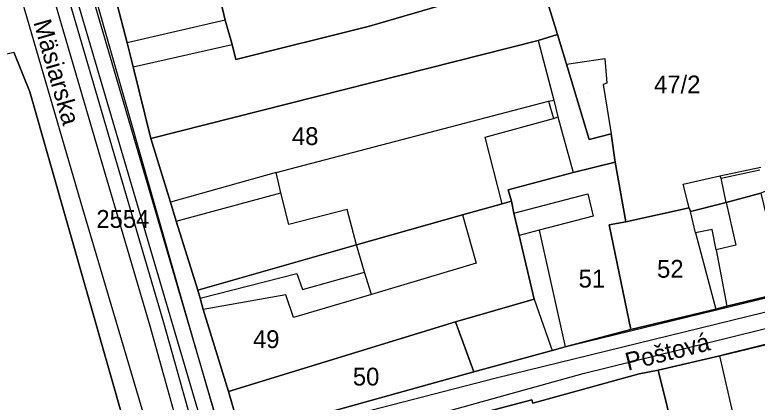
# Model space of a CAD drawing. Extents: x -263423 to -261326, y -1240067 to -1237864.
# Drawn here: x -263040 to -262956.7, y -1239293 to -1239249.5 of the extents above; entities that cross this region are included whole.
import ezdxf

# ---------------------------------------------------------------- set-up
doc = ezdxf.new("R2010")
doc.units = 0
for name, color, linetype in [('body_kn', 7, 'Continuous'), ('kladpar_druhypozemkov', 7, 'Continuous'), ('kladpar_hranice', 7, 'Continuous'), ('kladpar_parcelnecisla', 7, 'Continuous'), ('kladpar_plochy', 7, 'Continuous'), ('popisy', 7, 'Continuous'), ('tarchy_linie', 7, 'Continuous'), ('zappar_hrandruhpozemk', 7, 'Continuous')]:
    doc.layers.add(name, color=color, linetype=linetype)

msp = doc.modelspace()

# ---------------------------------------------------------------- linework, layer by layer
at = {"layer": 'body_kn'}
for p, q in [((-263016.37, -1239250.11), (-263016.37, -1239250.11)), ((-263016.37, -1239250.11), (-263016.37, -1239250.11)), ((-263000.2, -1239250.78), (-263000.2, -1239250.78)), ((-262981.26, -1239252.4), (-262981.26, -1239252.4)), ((-262981.26, -1239252.4), (-262981.26, -1239252.4)), ((-262979.09, -1239251.74), (-262979.09, -1239251.74)), ((-263027.4, -1239252.66), (-263027.4, -1239252.66)), ((-263015.6, -1239252.86), (-263015.6, -1239252.86)), ((-263015.2, -1239254.52), (-263015.2, -1239254.52)), ((-262973.76, -1239254.4), (-262973.76, -1239254.4)), ((-263026.7, -1239255.35), (-263026.7, -1239255.35)), ((-263026.7, -1239255.35), (-263026.7, -1239255.35)), ((-262978.09, -1239255.07), (-262978.09, -1239255.07)), ((-262978.09, -1239255.07), (-262978.09, -1239255.07)), ((-262973.95, -1239257.32), (-262973.95, -1239257.32)), ((-262973.56, -1239257.2), (-262973.56, -1239257.2)), ((-263038.31, -1239258.15), (-263038.31, -1239258.15)), ((-262979.51, -1239259.11), (-262979.51, -1239259.11)), ((-262979.51, -1239259.11), (-262979.51, -1239259.11)), ((-262980.08, -1239259.22), (-262980.08, -1239259.22)), ((-262979.55, -1239261.14), (-262979.55, -1239261.14)), ((-262979.55, -1239261.14), (-262979.55, -1239261.14)), ((-262979.04, -1239260.96), (-262979.04, -1239260.96)), ((-262987.21, -1239263.26), (-262987.21, -1239263.26)), ((-262973.05, -1239262.87), (-262973.05, -1239262.87)), ((-263024.72, -1239263.4), (-263024.72, -1239263.4)), ((-262975.54, -1239263.51), (-262975.54, -1239263.51)), ((-263030.37, -1239265.53), (-263030.37, -1239265.53)), ((-263028.88, -1239265.09), (-263028.88, -1239265.09)), ((-262972.62, -1239266.06), (-262972.62, -1239266.06)), ((-263010.65, -1239267.2), (-263010.65, -1239267.2)), ((-262977.34, -1239267.22), (-262977.34, -1239267.22)), ((-262977.34, -1239267.22), (-262977.34, -1239267.22)), ((-262960.85, -1239267.58), (-262960.85, -1239267.58)), ((-262960.73, -1239267.84), (-262960.73, -1239267.84)), ((-262960.73, -1239267.84), (-262960.73, -1239267.84)), ((-262984.61, -1239269.16), (-262984.61, -1239269.16)), ((-262964.99, -1239268.51), (-262964.99, -1239268.51)), ((-263010.13, -1239269.5), (-263010.13, -1239269.5)), ((-262975.68, -1239269.61), (-262975.68, -1239269.61)), ((-263022.53, -1239270.56), (-263022.53, -1239270.56)), ((-262985.28, -1239270.74), (-262985.28, -1239270.74)), ((-262985.28, -1239270.74), (-262985.28, -1239270.74)), ((-262984.26, -1239270.44), (-262984.26, -1239270.44)), ((-262960.15, -1239270.58), (-262960.15, -1239270.58)), ((-262960.15, -1239270.58), (-262960.15, -1239270.58)), ((-263032.38, -1239271.3), (-263032.38, -1239271.3)), ((-263002.68, -1239271.38), (-263002.68, -1239271.38)), ((-262964.29, -1239271.19), (-262964.29, -1239271.19)), ((-262964.29, -1239271.19), (-262964.29, -1239271.19)), ((-262964.17, -1239271.58), (-262964.17, -1239271.58)), ((-262989.75, -1239271.97), (-262989.75, -1239271.97)), ((-262989.75, -1239271.97), (-262989.75, -1239271.97)), ((-262983.97, -1239271.78), (-262983.97, -1239271.78)), ((-262983.97, -1239271.78), (-262983.97, -1239271.78)), ((-262975.1, -1239272.1), (-262975.1, -1239272.1)), ((-263021.88, -1239272.67), (-263021.88, -1239272.67)), ((-263021.88, -1239272.67), (-263021.88, -1239272.67)), ((-263009.26, -1239273.07), (-263009.26, -1239273.07)), ((-262973.28, -1239273.1), (-262973.28, -1239273.1)), ((-262971.43, -1239272.75), (-262971.43, -1239272.75)), ((-262981.16, -1239273.69), (-262981.16, -1239273.69)), ((-262963.59, -1239274), (-262963.59, -1239274)), ((-262961.74, -1239273.6), (-262961.74, -1239273.6)), ((-262983.39, -1239274.27), (-262983.39, -1239274.27)), ((-263001.63, -1239275.34), (-263001.63, -1239275.34)), ((-263001.63, -1239275.34), (-263001.63, -1239275.34)), ((-262959.05, -1239275.37), (-262959.05, -1239275.37)), ((-262961.28, -1239275.9), (-262961.28, -1239275.9)), ((-262961.28, -1239275.9), (-262961.28, -1239275.9)), ((-262988.22, -1239277.41), (-262988.22, -1239277.41)), ((-263008.36, -1239278.56), (-263008.36, -1239278.56)), ((-263000.74, -1239278.41), (-263000.74, -1239278.41)), ((-263019.44, -1239280.42), (-263019.44, -1239280.42)), ((-263007.7, -1239280.35), (-263007.7, -1239280.35)), ((-263019.21, -1239281.31), (-263019.21, -1239281.31)), ((-263019.21, -1239281.31), (-263019.21, -1239281.31)), ((-263009.56, -1239280.95), (-263009.56, -1239280.95)), ((-262999.97, -1239280.9), (-262999.97, -1239280.9)), ((-262981.71, -1239281.43), (-262981.71, -1239281.43)), ((-262981.71, -1239281.43), (-262981.71, -1239281.43)), ((-263021.19, -1239281.84), (-263021.19, -1239281.84)), ((-262960.09, -1239282.21), (-262960.09, -1239282.21)), ((-263018.86, -1239282.59), (-263018.86, -1239282.59)), ((-262961.3, -1239282.57), (-262961.3, -1239282.57)), ((-262961.3, -1239282.57), (-262961.3, -1239282.57)), ((-263023.3, -1239284.05), (-263023.3, -1239284.05)), ((-263008.72, -1239283.51), (-263008.72, -1239283.51)), ((-262990.52, -1239283.97), (-262990.52, -1239283.97)), ((-262990.52, -1239283.97), (-262990.52, -1239283.97)), ((-263024.79, -1239284.47), (-263024.79, -1239284.47)), ((-262970.87, -1239284.84), (-262970.87, -1239284.84)), ((-262977.34, -1239286.55), (-262977.34, -1239286.55)), ((-262979.68, -1239287.19), (-262979.68, -1239287.19)), ((-262978.21, -1239286.78), (-262978.21, -1239286.78)), ((-262960.85, -1239287.79), (-262960.85, -1239287.79)), ((-262960.14, -1239287.62), (-262960.14, -1239287.62)), ((-262988.49, -1239289.6), (-262988.49, -1239289.6)), ((-262976.2, -1239289.79), (-262976.2, -1239289.79)), ((-262969.9, -1239289.82), (-262969.9, -1239289.82)), ((-262967.8, -1239289.42), (-262967.8, -1239289.42)), ((-262985.96, -1239290.25), (-262985.96, -1239290.25)), ((-263016.01, -1239291.8), (-263016.01, -1239291.8)), ((-262981.96, -1239292.73), (-262981.96, -1239292.73)), ((-262981.96, -1239292.73), (-262981.96, -1239292.73))]:
    msp.add_line(p, q, dxfattribs=at)
at = {"layer": 'kladpar_druhypozemkov'}
for p, q in [((-262965.58, -1239256.03), (-262965.58, -1239256.03)), ((-262975.74, -1239258.24), (-262975.74, -1239258.24)), ((-263007.48, -1239262.23), (-263007.48, -1239262.23)), ((-263027.11, -1239271.58), (-263027.11, -1239271.58)), ((-262966.58, -1239277.03), (-262966.58, -1239277.03)), ((-262975.98, -1239278.03), (-262975.98, -1239278.03)), ((-263012.08, -1239285.23), (-263012.08, -1239285.23)), ((-263000.78, -1239289.03), (-263000.78, -1239289.03))]:
    msp.add_line(p, q, dxfattribs=at)
at = {"layer": 'kladpar_hranice'}
for points in [[(-263035.52, -1239214.87), (-263035.24, -1239216.53), (-263034.28, -1239221.95), (-263034, -1239223.61), (-263032.86, -1239229.54), (-263032.46, -1239231.84), (-263031.14, -1239237.84), (-263029.91, -1239242.76), (-263029.62, -1239244.1), (-263029.39, -1239244.87), (-263027.4, -1239252.66), (-263026.7, -1239255.35), (-263024.72, -1239263.4), (-263022.53, -1239270.56), (-263021.88, -1239272.67), (-263019.44, -1239280.42), (-263019.21, -1239281.31), (-263018.86, -1239282.59), (-263016.01, -1239291.8), (-263014.54, -1239296.85)], [(-262972.87, -1239231.29), (-262968.72, -1239230.3), (-262966.96, -1239236.76), (-262966.32, -1239239.25), (-262966.03, -1239240.53), (-262968.71, -1239241.17), (-262967.78, -1239245), (-262964.91, -1239244.43), (-262964.73, -1239245.13), (-262980.22, -1239248.1), (-262980.39, -1239247.33), (-262979.88, -1239247.28), (-262980.4, -1239244.98), (-263000.2, -1239250.78), (-263015.2, -1239254.52), (-263015.6, -1239252.86), (-263016.37, -1239250.11), (-263016.89, -1239248.06), (-262981.99, -1239239.29), (-262982.17, -1239238.65), (-262979.42, -1239237.89), (-262980.72, -1239233.28), (-262972.87, -1239231.29)], [(-263016.25, -1239241.85), (-263002.28, -1239238.66), (-262998.77, -1239237.78), (-262991.75, -1239236.03), (-262983.46, -1239233.98), (-262982.17, -1239238.65), (-262981.99, -1239239.29), (-263016.89, -1239248.06), (-263016.37, -1239250.11), (-263015.6, -1239252.86), (-263015.2, -1239254.52), (-263000.2, -1239250.78), (-262980.4, -1239244.98), (-262979.88, -1239247.28), (-262980.39, -1239247.33), (-262980.22, -1239248.1), (-262979.09, -1239251.74), (-262981.26, -1239252.4), (-263024.72, -1239263.4), (-263026.7, -1239255.35), (-263027.4, -1239252.66), (-263029.39, -1239244.87), (-263016.25, -1239241.85)], [(-262955.94, -1239243.48), (-262954.51, -1239250.69), (-262954.1, -1239252.29), (-262950.77, -1239268.18), (-262955.49, -1239269.29), (-262955.81, -1239269.34), (-262956.26, -1239269.53), (-262960.15, -1239270.58), (-262964.17, -1239271.58), (-262964.29, -1239271.19), (-262971.43, -1239272.75), (-262972.62, -1239266.06), (-262973.05, -1239262.87), (-262975.54, -1239263.51), (-262978.09, -1239255.07), (-262979.09, -1239251.74), (-262980.22, -1239248.1), (-262964.73, -1239245.13), (-262955.94, -1239243.48)], [(-262981.26, -1239252.4), (-262979.09, -1239251.74), (-262978.09, -1239255.07), (-262975.54, -1239263.51), (-262973.05, -1239262.87), (-262972.62, -1239266.06), (-262977.34, -1239267.22), (-262984.61, -1239269.16), (-262984.26, -1239270.44), (-262985.28, -1239270.74), (-262989.75, -1239271.97), (-263001.63, -1239275.34), (-263019.44, -1239280.42), (-263021.88, -1239272.67), (-263022.53, -1239270.56), (-263024.72, -1239263.4), (-262981.26, -1239252.4)], [(-263096.55, -1239289.29), (-263050.66, -1239278.61), (-263051.53, -1239274.75), (-263048.53, -1239274.04), (-263049.83, -1239268.51), (-263053.08, -1239269.2), (-263055.87, -1239257.45), (-263054.98, -1239257.21), (-263040.12, -1239253.72), (-263038.31, -1239258.15), (-263027.41, -1239296.38), (-263069.94, -1239305.75), (-263095.43, -1239310.79), (-263095.55, -1239310.47), (-263096.38, -1239301.87), (-263096.18, -1239301.56), (-263096.19, -1239301.34), (-263096.55, -1239289.29)], [(-263027.41, -1239296.38), (-263038.31, -1239258.15), (-263040.12, -1239253.72)], [(-262977.34, -1239267.22), (-262972.62, -1239266.06), (-262971.43, -1239272.75), (-262973.28, -1239273.1), (-262970.87, -1239284.84), (-262978.21, -1239286.78), (-262979.68, -1239287.19), (-262988.49, -1239289.6), (-262990.52, -1239283.97), (-262981.71, -1239281.43), (-262983.39, -1239274.27), (-262983.97, -1239271.78), (-262984.26, -1239270.44), (-262984.61, -1239269.16), (-262977.34, -1239267.22)], [(-262961.3, -1239282.57), (-262960.09, -1239282.21), (-262953.58, -1239280.64), (-262938.79, -1239277.28), (-262934.71, -1239276.35), (-262916.67, -1239272.67), (-262899.14, -1239269.31), (-262898.86, -1239273.95), (-262909.51, -1239276.2), (-262909.57, -1239275.82), (-262930.73, -1239280.44), (-262947.83, -1239284.64), (-262960.85, -1239287.79), (-262967.8, -1239289.42), (-262969.9, -1239289.82), (-262981.84, -1239293.12), (-262981.96, -1239292.73), (-262996.58, -1239296.61)], [(-262964.29, -1239271.19), (-262964.17, -1239271.58), (-262960.15, -1239270.58), (-262956.26, -1239269.53), (-262953.58, -1239280.64), (-262960.09, -1239282.21), (-262961.3, -1239282.57), (-262970.87, -1239284.84), (-262973.28, -1239273.1), (-262971.43, -1239272.75), (-262964.29, -1239271.19)], [(-263001.63, -1239275.34), (-262989.75, -1239271.97), (-262985.28, -1239270.74), (-262984.26, -1239270.44), (-262983.97, -1239271.78), (-262983.39, -1239274.27), (-262981.71, -1239281.43), (-262990.52, -1239283.97), (-263016.01, -1239291.8), (-263018.86, -1239282.59), (-263019.21, -1239281.31), (-263019.44, -1239280.42), (-263001.63, -1239275.34)], [(-263014.54, -1239296.85), (-262988.49, -1239289.6), (-262979.68, -1239287.19), (-262978.21, -1239286.78), (-262970.87, -1239284.84), (-262961.3, -1239282.57)], [(-262990.52, -1239283.97), (-262988.49, -1239289.6), (-263014.54, -1239296.85), (-263016.01, -1239291.8), (-262990.52, -1239283.97)], [(-262947.83, -1239284.64), (-262942.65, -1239308.58), (-262955.4, -1239311.48), (-262961.85, -1239313.44), (-262967.8, -1239289.42), (-262960.85, -1239287.79), (-262947.83, -1239284.64)], [(-262981.96, -1239292.73), (-262981.84, -1239293.12), (-262969.9, -1239289.82), (-262967.8, -1239289.42), (-262961.85, -1239313.44), (-262969.39, -1239315.56), (-262979.22, -1239318.08), (-262986.1, -1239319.71), (-262986.05, -1239319.97), (-262987.45, -1239320.25), (-262986.7, -1239323.64), (-263004, -1239328.6), (-263005.55, -1239324.05), (-263006.38, -1239321.43), (-263013.25, -1239301.58), (-262996.46, -1239296.99), (-262996.58, -1239296.61), (-262981.96, -1239292.73)]]:
    msp.add_lwpolyline(points, dxfattribs=at)
at = {"layer": 'kladpar_plochy'}
for points in [[(-262972.87, -1239231.29), (-262968.72, -1239230.3), (-262966.96, -1239236.76), (-262966.32, -1239239.25), (-262966.03, -1239240.53), (-262968.71, -1239241.17), (-262967.78, -1239245), (-262964.91, -1239244.43), (-262964.73, -1239245.13), (-262980.22, -1239248.1), (-262980.39, -1239247.33), (-262979.88, -1239247.28), (-262980.4, -1239244.98), (-263000.2, -1239250.78), (-263015.2, -1239254.52), (-263015.6, -1239252.86), (-263016.37, -1239250.11), (-263016.89, -1239248.06), (-262981.99, -1239239.29), (-262982.17, -1239238.65), (-262979.42, -1239237.89), (-262980.72, -1239233.28)], [(-263016.25, -1239241.85), (-263002.28, -1239238.66), (-262998.77, -1239237.78), (-262991.75, -1239236.03), (-262983.46, -1239233.98), (-262982.17, -1239238.65), (-262981.99, -1239239.29), (-263016.89, -1239248.06), (-263016.37, -1239250.11), (-263015.6, -1239252.86), (-263015.2, -1239254.52), (-263000.2, -1239250.78), (-262980.4, -1239244.98), (-262979.88, -1239247.28), (-262980.39, -1239247.33), (-262980.22, -1239248.1), (-262979.09, -1239251.74), (-262981.26, -1239252.4), (-263024.72, -1239263.4), (-263026.7, -1239255.35), (-263027.4, -1239252.66), (-263029.39, -1239244.87)], [(-262955.94, -1239243.48), (-262954.51, -1239250.69), (-262954.1, -1239252.29), (-262950.77, -1239268.18), (-262955.49, -1239269.29), (-262955.81, -1239269.34), (-262956.26, -1239269.53), (-262960.15, -1239270.58), (-262964.17, -1239271.58), (-262964.29, -1239271.19), (-262971.43, -1239272.75), (-262972.62, -1239266.06), (-262973.05, -1239262.87), (-262975.54, -1239263.51), (-262978.09, -1239255.07), (-262979.09, -1239251.74), (-262980.22, -1239248.1), (-262964.73, -1239245.13)], [(-262981.26, -1239252.4), (-262979.09, -1239251.74), (-262978.09, -1239255.07), (-262975.54, -1239263.51), (-262973.05, -1239262.87), (-262972.62, -1239266.06), (-262977.34, -1239267.22), (-262984.61, -1239269.16), (-262984.26, -1239270.44), (-262985.28, -1239270.74), (-262989.75, -1239271.97), (-263001.63, -1239275.34), (-263019.44, -1239280.42), (-263021.88, -1239272.67), (-263022.53, -1239270.56), (-263024.72, -1239263.4)], [(-263096.55, -1239289.29), (-263050.66, -1239278.61), (-263051.53, -1239274.75), (-263048.53, -1239274.04), (-263049.83, -1239268.51), (-263053.08, -1239269.2), (-263055.87, -1239257.45), (-263054.98, -1239257.21), (-263040.12, -1239253.72), (-263038.31, -1239258.15), (-263027.41, -1239296.38), (-263069.94, -1239305.75), (-263095.43, -1239310.79), (-263095.55, -1239310.47), (-263096.38, -1239301.87), (-263096.18, -1239301.56), (-263096.19, -1239301.34)], [(-262977.34, -1239267.22), (-262972.62, -1239266.06), (-262971.43, -1239272.75), (-262973.28, -1239273.1), (-262970.87, -1239284.84), (-262978.21, -1239286.78), (-262979.68, -1239287.19), (-262988.49, -1239289.6), (-262990.52, -1239283.97), (-262981.71, -1239281.43), (-262983.39, -1239274.27), (-262983.97, -1239271.78), (-262984.26, -1239270.44), (-262984.61, -1239269.16)], [(-262964.29, -1239271.19), (-262964.17, -1239271.58), (-262960.15, -1239270.58), (-262956.26, -1239269.53), (-262953.58, -1239280.64), (-262960.09, -1239282.21), (-262961.3, -1239282.57), (-262970.87, -1239284.84), (-262973.28, -1239273.1), (-262971.43, -1239272.75)], [(-263001.63, -1239275.34), (-262989.75, -1239271.97), (-262985.28, -1239270.74), (-262984.26, -1239270.44), (-262983.97, -1239271.78), (-262983.39, -1239274.27), (-262981.71, -1239281.43), (-262990.52, -1239283.97), (-263016.01, -1239291.8), (-263018.86, -1239282.59), (-263019.21, -1239281.31), (-263019.44, -1239280.42)], [(-262990.52, -1239283.97), (-262988.49, -1239289.6), (-263014.54, -1239296.85), (-263016.01, -1239291.8)], [(-262947.83, -1239284.64), (-262942.65, -1239308.58), (-262955.4, -1239311.48), (-262961.85, -1239313.44), (-262967.8, -1239289.42), (-262960.85, -1239287.79)], [(-262981.96, -1239292.73), (-262981.84, -1239293.12), (-262969.9, -1239289.82), (-262967.8, -1239289.42), (-262961.85, -1239313.44), (-262969.39, -1239315.56), (-262979.22, -1239318.08), (-262986.1, -1239319.71), (-262986.05, -1239319.97), (-262987.45, -1239320.25), (-262986.7, -1239323.64), (-263004, -1239328.6), (-263005.55, -1239324.05), (-263006.38, -1239321.43), (-263013.25, -1239301.58), (-262996.46, -1239296.99), (-262996.58, -1239296.61)]]:
    msp.add_lwpolyline(points, close=True, dxfattribs=at)
for points in [[(-263029.39, -1239244.87), (-263027.4, -1239252.66), (-263026.7, -1239255.35), (-263024.72, -1239263.4), (-263022.53, -1239270.56), (-263021.88, -1239272.67), (-263019.44, -1239280.42), (-263019.21, -1239281.31), (-263018.86, -1239282.59), (-263016.01, -1239291.8), (-263014.54, -1239296.85)], [(-263027.41, -1239296.38), (-263038.31, -1239258.15), (-263040.12, -1239253.72)], [(-263014.54, -1239296.85), (-262988.49, -1239289.6), (-262979.68, -1239287.19), (-262978.21, -1239286.78), (-262970.87, -1239284.84), (-262961.3, -1239282.57), (-262960.09, -1239282.21), (-262953.58, -1239280.64), (-262938.79, -1239277.28), (-262934.71, -1239276.35), (-262916.67, -1239272.67), (-262899.14, -1239269.31), (-262898.86, -1239273.95), (-262909.51, -1239276.2), (-262909.57, -1239275.82), (-262930.73, -1239280.44), (-262947.83, -1239284.64), (-262960.85, -1239287.79), (-262967.8, -1239289.42), (-262969.9, -1239289.82), (-262981.84, -1239293.12), (-262981.96, -1239292.73), (-262996.58, -1239296.61)]]:
    msp.add_lwpolyline(points, dxfattribs=at)
at = {"layer": 'tarchy_linie'}
for points in [[(-263066.63, -1239074.68), (-263054.28, -1239131.66), (-263044.07, -1239188.4), (-263040.31, -1239208.42), (-263033.52, -1239246.09), (-263017.34, -1239301.19)], [(-263064.97, -1239074.32), (-263052.62, -1239131.34), (-263043.78, -1239180.54), (-263042.45, -1239183.02), (-263038.09, -1239208.38), (-263038.42, -1239209.31), (-263031.96, -1239245.18), (-263015.67, -1239300.72), (-263012.86, -1239310.78), (-263008.84, -1239324.01), (-263001.88, -1239346.16), (-262996.25, -1239368.2), (-262982.01, -1239418.22)], [(-263020.65, -1239299.35), (-263024.79, -1239284.47), (-263030.37, -1239265.53), (-263036.29, -1239245.27), (-263039.21, -1239229.72), (-263041.4, -1239216.31), (-263041.14, -1239214.25), (-263041.91, -1239211.3), (-263041.7, -1239210.32), (-263041.97, -1239208.72), (-263045.72, -1239188.7), (-263047.17, -1239180.64), (-263048.17, -1239178.9), (-263052.43, -1239156.39), (-263054.49, -1239142.21), (-263054.74, -1239142.2), (-263056.2, -1239134.52), (-263061.14, -1239108.88), (-263067.31, -1239082.07)], [(-263065.8, -1239081.72), (-263059.62, -1239108.59), (-263054.68, -1239134.23), (-263053.44, -1239140.73), (-263053.14, -1239140.75), (-263050.91, -1239156.11), (-263046.81, -1239178.15), (-263043.98, -1239183.29), (-263039.59, -1239207.97), (-263040.4, -1239210.96), (-263039.61, -1239214.51), (-263039.87, -1239216.06), (-263037.69, -1239229.43), (-263034.8, -1239244.84), (-263028.88, -1239265.09), (-263023.3, -1239284.05), (-263019.3, -1239298.33), (-263019.19, -1239298.83), (-263016.92, -1239305.25), (-263015.38, -1239307.81), (-263010.32, -1239324.47), (-263003.38, -1239346.54), (-262997.74, -1239368.62), (-262983.51, -1239418.62)], [(-263016.43, -1239298.12), (-262985.96, -1239290.25), (-262934.76, -1239277.75), (-262904.17, -1239271.89), (-262892.84, -1239270.34)], [(-263015.67, -1239300.73), (-262976.2, -1239289.79), (-262934.19, -1239279.4), (-262892.68, -1239271.23)], [(-263014.54, -1239296.85), (-262988.49, -1239289.6), (-262979.68, -1239287.19), (-262978.21, -1239286.78), (-262977.34, -1239286.55), (-262947.14, -1239279.18)], [(-262933.81, -1239281.11), (-262960.14, -1239287.62), (-262960.85, -1239287.79), (-262967.8, -1239289.42), (-262969.9, -1239289.82), (-262981.84, -1239293.12), (-262981.96, -1239292.73), (-262996.58, -1239296.61)]]:
    msp.add_lwpolyline(points, dxfattribs=at)
at = {"layer": 'zappar_hrandruhpozemk'}
for p, q in [((-263016.37, -1239250.11), (-263027.4, -1239252.66)), ((-262981.26, -1239252.4), (-262979.51, -1239259.11)), ((-263026.7, -1239255.35), (-263015.6, -1239252.86)), ((-262973.95, -1239257.32), (-262973.05, -1239262.87)), ((-262980.08, -1239259.22), (-262979.51, -1239259.11)), ((-263010.65, -1239267.2), (-262980.08, -1239259.22)), ((-262980.08, -1239259.22), (-262979.55, -1239261.14)), ((-262987.21, -1239263.26), (-262979.55, -1239261.14)), ((-262979.55, -1239261.14), (-262979.04, -1239260.96)), ((-262985.28, -1239270.74), (-262987.21, -1239263.26)), ((-263010.65, -1239267.2), (-263022.53, -1239270.56)), ((-262960.73, -1239267.84), (-262956.39, -1239266.92)), ((-262964.29, -1239271.19), (-262964.99, -1239268.51)), ((-263021.88, -1239272.67), (-263010.13, -1239269.5)), ((-262963.59, -1239274), (-262964.17, -1239271.58)), ((-262989.75, -1239271.97), (-262988.22, -1239277.41)), ((-262975.1, -1239272.1), (-262981.16, -1239273.69)), ((-262981.16, -1239273.69), (-262983.39, -1239274.27)), ((-262981.16, -1239273.69), (-262978.21, -1239286.78)), ((-262963.59, -1239274), (-262961.3, -1239282.57)), ((-262961.28, -1239275.9), (-262960.09, -1239282.21)), ((-262988.22, -1239277.41), (-262999.97, -1239280.9)), ((-262981.71, -1239281.43), (-262979.68, -1239287.19)), ((-262955.4, -1239311.48), (-262960.85, -1239287.79))]:
    msp.add_line(p, q, dxfattribs=at)
for points in [[(-263026.65, -1239299.26), (-263025.94, -1239298.77), (-263025.42, -1239298.08), (-263025.08, -1239297.45), (-263024.94, -1239296.82), (-263025.11, -1239295.8), (-263032.38, -1239271.3), (-263039.87, -1239245.47), (-263044.79, -1239215.3), (-263047.8, -1239196.24)], [(-263039.69, -1239199.46), (-263034.27, -1239230.15), (-263031.91, -1239244.18), (-263021.19, -1239281.84), (-263017.06, -1239296.1), (-263016.57, -1239296.87), (-263015.81, -1239297.08), (-263015.24, -1239297.09), (-263014.54, -1239296.85)], [(-262978.09, -1239255.07), (-262973.76, -1239254.4), (-262973.56, -1239257.2), (-262973.95, -1239257.32)], [(-262979.51, -1239259.11), (-262979.04, -1239260.96), (-262977.34, -1239267.22)], [(-262964.99, -1239268.51), (-262960.85, -1239267.58), (-262956.26, -1239266.6)], [(-263001.63, -1239275.34), (-263002.68, -1239271.38), (-263009.26, -1239273.07), (-263010.13, -1239269.5), (-263010.65, -1239267.2)], [(-262960.15, -1239270.58), (-262960.73, -1239267.84), (-262960.85, -1239267.58)], [(-262983.97, -1239271.78), (-262975.68, -1239269.61), (-262975.1, -1239272.1)], [(-262960.15, -1239270.58), (-262959.05, -1239275.37), (-262961.28, -1239275.9), (-262961.74, -1239273.6), (-262963.59, -1239274)], [(-262999.97, -1239280.9), (-263000.74, -1239278.41), (-263001.63, -1239275.34)], [(-263019.21, -1239281.31), (-263008.36, -1239278.56), (-263007.7, -1239280.35), (-263000.74, -1239278.41)], [(-262999.97, -1239280.9), (-263008.72, -1239283.51), (-263009.56, -1239280.95), (-263018.86, -1239282.59)]]:
    msp.add_lwpolyline(points, dxfattribs=at)

# ---------------------------------------------------------------- texts
at = {"layer": 'kladpar_parcelnecisla'}
for s, p in [('47/2', (-262968.247, -1239258.33)), ('48', (-263008.892, -1239264.13)), ('52', (-262967.91, -1239279.03)), ('51', (-262976.714, -1239280.13)), ('49', (-263013.268, -1239286.93)), ('50', (-263002.055, -1239291.13))]:
    msp.add_text(s, height=2, dxfattribs=at).set_placement(p)
msp.add_text('2554', height=2, rotation=360, dxfattribs=at).set_placement((-263030.847, -1239273.43))
at = {"layer": 'popisy'}
for s, rotation, p in [('Mäsiarska', 286, (-263037.933, -1239250.34)), ('Poštová', 14, (-262971.19, -1239289.473))]:
    msp.add_text(s, height=2, rotation=rotation, dxfattribs=at).set_placement(p)

doc.saveas('drawing.dxf')
